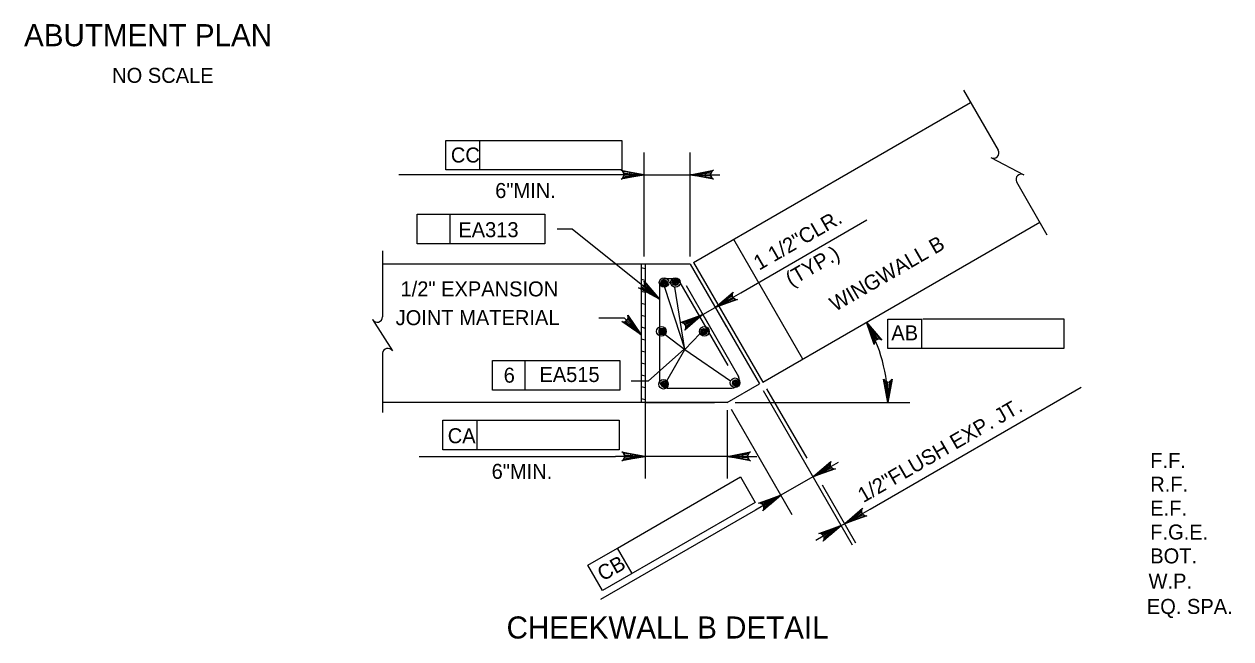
# Model space of a CAD drawing. Extents: x 638255 to 640306, y 296059 to 298435.
# Drawn here: x 638706.2 to 638947.5, y 297517 to 297639.9 of the extents above; entities that cross this region are included whole.
import ezdxf

# ---------------------------------------------------------------- set-up
doc = ezdxf.new("R2010")
doc.units = 0
for name, color, linetype in [('1', 7, 'Continuous'), ('Level 10', 7, 'Continuous'), ('Level 3', 7, 'Continuous'), ('Level 4', 7, 'Continuous'), ('Level 5', 7, 'Continuous')]:
    doc.layers.add(name, color=color, linetype=linetype)

# ---------------------------------------------------------------- blocks, each defined once
blk = doc.blocks.new('V')
at = {"layer": '1'}
blk.add_line((0, 0), (0, 0), dxfattribs=at)

msp = doc.modelspace()

# ---------------------------------------------------------------- linework, layer by layer
at = {"layer": 'Level 10'}
for p, q in [((638840.08, 297592.3), (638895.47, 297624.28)), ((638853.9, 297568.37), (638909.29, 297600.35)), ((638848.06, 297596.91), (638861.88, 297572.98)), ((638839.42, 297591.92), (638777.88, 297591.92)), ((638839.42, 297591.92), (638853.23, 297567.99)), ((638840.08, 297592.3), (638853.9, 297568.37)), ((638846.82, 297564.29), (638853.23, 297567.99)), ((638846.82, 297564.29), (638777.88, 297564.29)), ((638830.38, 297564.29), (638844.28, 297564.29))]:
    msp.add_line(p, q, dxfattribs=at)
at = {"layer": 'Level 3'}
for p, q in [((638790.51, 297616.67), (638797.34, 297616.67)), ((638790.51, 297610.78), (638790.51, 297616.67)), ((638797.34, 297610.78), (638797.34, 297616.67)), ((638797.34, 297616.67), (638825.74, 297616.67)), ((638825.74, 297616.67), (638825.74, 297610.78)), ((638830.21, 297593.45), (638830.21, 297614.24)), ((638839.42, 297593.45), (638839.42, 297614.24)), ((638827.26, 297609.83), (638781.13, 297609.83)), ((638825.74, 297610.78), (638790.51, 297610.78)), ((638830.21, 297609.83), (638839.42, 297609.83)), ((638842.36, 297609.83), (638845.31, 297609.83)), ((638784.82, 297601.9), (638810.31, 297601.9)), ((638784.82, 297596.01), (638784.82, 297601.9)), ((638791.4, 297596.01), (638791.4, 297601.9)), ((638810.31, 297601.9), (638810.31, 297596.01)), ((638849.51, 297586.22), (638874.73, 297600.78)), ((638815.77, 297598.94), (638812.82, 297598.94)), ((638833.26, 297584.95), (638815.77, 297598.94)), ((638810.31, 297596.01), (638784.82, 297596.01)), ((638829.61, 297591.92), (638829.61, 297564.29)), ((638829.61, 297591.3), (638830.38, 297591.09)), ((638830.38, 297591.92), (638830.38, 297562.75)), ((638829.61, 297588.91), (638830.38, 297588.71)), ((638834.79, 297589.04), (638835.98, 297589.04)), ((638837.31, 297588.27), (638846.91, 297571.65)), ((638829.61, 297586.53), (638830.38, 297586.32)), ((638833.26, 297587.5), (638833.26, 297568.7)), ((638834.26, 297587.31), (638838.31, 297574.9)), ((638838.31, 297574.9), (638836.3, 297587.32)), ((638838.56, 297587.65), (638849.05, 297569.47)), ((638842.36, 297586.83), (638846.62, 297579.45)), ((638844.4, 297583.28), (638849.51, 297586.22)), ((638829.61, 297584.15), (638830.38, 297583.94)), ((638841.91, 297581.84), (638844.41, 297583.28)), ((638826.28, 297581.15), (638821.13, 297581.15)), ((638829.61, 297577.81), (638826.28, 297581.15)), ((638829.61, 297581.76), (638830.38, 297581.56)), ((638841.53, 297582.51), (638843.5, 297579.09)), ((638878.9, 297575.04), (638878.9, 297580.94)), ((638878.9, 297580.94), (638885.71, 297580.94)), ((638885.73, 297575.04), (638885.73, 297580.94)), ((638885.94, 297580.99), (638914.18, 297580.99)), ((638914.13, 297580.94), (638914.13, 297575.04)), ((638829.61, 297579.38), (638830.38, 297579.17)), ((638829.61, 297577), (638830.38, 297576.79)), ((638834.36, 297577.86), (638838.31, 297574.9)), ((638838.31, 297574.9), (638841.37, 297578.1)), ((638829.61, 297574.61), (638830.38, 297574.4)), ((638838.27, 297575.03), (638831.02, 297568.51)), ((638834.72, 297568.63), (638838.31, 297574.9)), ((638838.31, 297574.9), (638847.48, 297568.59)), ((638914.13, 297575.04), (638878.9, 297575.04)), ((638799.85, 297572.65), (638825.33, 297572.65)), ((638799.85, 297566.76), (638799.85, 297572.65)), ((638806.42, 297566.76), (638806.42, 297572.65)), ((638825.33, 297572.65), (638825.33, 297566.76)), ((638829.61, 297572.23), (638830.38, 297572.02)), ((638831.02, 297568.51), (638827.61, 297568.51)), ((638829.61, 297569.84), (638830.38, 297569.64)), ((638825.33, 297566.76), (638799.85, 297566.76)), ((638829.61, 297567.46), (638830.38, 297567.25)), ((638834.79, 297567.17), (638847.73, 297567.17)), ((638854, 297566.66), (638871.8, 297535.82)), ((638854.67, 297567.04), (638862.69, 297553.15)), ((638875.36, 297542.98), (638917.55, 297567.34)), ((638829.61, 297565.08), (638830.38, 297564.87)), ((638848.36, 297564.29), (638883.34, 297564.29)), ((638830.38, 297562.75), (638830.38, 297549.09)), ((638846.82, 297562.75), (638846.82, 297549.09)), ((638847.59, 297562.96), (638859.75, 297541.89)), ((638789.95, 297560.73), (638796.79, 297560.73)), ((638789.95, 297554.84), (638789.95, 297560.73)), ((638796.79, 297554.84), (638796.79, 297560.73)), ((638796.79, 297560.73), (638825.19, 297560.73)), ((638825.19, 297560.73), (638825.19, 297554.84)), ((638825.19, 297554.84), (638789.95, 297554.84)), ((638785.18, 297553.5), (638824.48, 297553.5)), ((638827.43, 297553.5), (638824.48, 297553.5)), ((638846.82, 297553.5), (638830.38, 297553.5)), ((638849.77, 297553.5), (638852.72, 297553.5)), ((638863.95, 297549.42), (638869.06, 297552.37)), ((638824.84, 297535.18), (638849.43, 297549.38)), ((638849.43, 297549.38), (638852.38, 297544.28)), ((638863.95, 297549.42), (638857.54, 297545.72)), ((638865.78, 297547.8), (638872.47, 297536.21)), ((638857.54, 297545.72), (638852.44, 297542.77)), ((638852.44, 297542.77), (638821.49, 297524.91)), ((638852.38, 297544.28), (638821.87, 297526.66)), ((638870.26, 297540.04), (638875.36, 297542.98)), ((638869.6, 297539.65), (638864.49, 297536.71)), ((638869.6, 297539.65), (638870.26, 297540.03)), ((638818.92, 297531.76), (638824.84, 297535.18)), ((638827.78, 297530.08), (638824.84, 297535.18)), ((638821.87, 297526.66), (638818.92, 297531.76))]:
    msp.add_line(p, q, dxfattribs=at)
for points in [[(638830.21, 297609.83), (638825.56, 297608.95), (638825.92, 297609.2), (638826.1, 297609.51), (638826.15, 297609.83), (638826.1, 297610.14), (638825.92, 297610.45), (638825.56, 297610.7), (638830.21, 297609.83), (638825.92, 297610.45), (638826.1, 297610.14), (638830.21, 297609.83), (638826.15, 297609.83), (638826.1, 297609.51), (638830.21, 297609.83), (638825.92, 297609.2)], [(638839.42, 297609.83), (638844.07, 297610.7), (638843.71, 297610.45), (638843.53, 297610.14), (638843.47, 297609.83), (638843.53, 297609.51), (638843.71, 297609.2), (638844.07, 297608.95), (638839.42, 297609.83), (638843.71, 297609.2), (638843.53, 297609.51), (638839.42, 297609.83), (638843.47, 297609.83), (638843.53, 297610.14), (638839.42, 297609.83), (638843.71, 297610.45)], [(638833.26, 297584.95), (638829.08, 297587.18), (638829.51, 297587.15), (638829.85, 297587.28), (638830.09, 297587.49), (638830.24, 297587.76), (638830.29, 297588.12), (638830.17, 297588.54), (638833.26, 297584.95), (638830.29, 297588.12), (638830.24, 297587.76), (638833.26, 297584.95), (638830.09, 297587.49), (638829.85, 297587.28), (638833.26, 297584.95), (638829.51, 297587.15)], [(638844.4, 297583.28), (638848, 297586.36), (638847.81, 297585.96), (638847.81, 297585.6), (638847.92, 297585.3), (638848.12, 297585.06), (638848.43, 297584.88), (638848.87, 297584.85), (638844.4, 297583.28), (638848.43, 297584.88), (638848.12, 297585.06), (638844.4, 297583.28), (638847.92, 297585.3), (638847.81, 297585.6), (638844.4, 297583.28), (638847.81, 297585.96)], [(638829.61, 297577.81), (638825.71, 297580.49), (638826.14, 297580.41), (638826.49, 297580.5), (638826.75, 297580.68), (638826.93, 297580.94), (638827.02, 297581.29), (638826.94, 297581.72), (638829.61, 297577.81), (638827.02, 297581.29), (638826.93, 297580.94), (638829.61, 297577.81), (638826.75, 297580.68), (638826.49, 297580.5), (638829.61, 297577.81), (638826.14, 297580.41)], [(638841.91, 297581.84), (638838.32, 297578.76), (638838.51, 297579.15), (638838.51, 297579.51), (638838.4, 297579.81), (638838.2, 297580.05), (638837.88, 297580.23), (638837.45, 297580.27), (638841.91, 297581.84), (638837.88, 297580.23), (638838.2, 297580.05), (638841.91, 297581.84), (638838.4, 297579.81), (638838.51, 297579.51), (638841.91, 297581.84), (638838.51, 297579.15)], [(638874.62, 297580.34), (638877.7, 297576.75), (638877.31, 297576.93), (638876.95, 297576.94), (638876.65, 297576.83), (638876.41, 297576.62), (638876.23, 297576.31), (638876.19, 297575.87), (638874.62, 297580.34), (638876.23, 297576.31), (638876.41, 297576.62), (638874.62, 297580.34), (638876.65, 297576.83), (638876.95, 297576.94), (638874.62, 297580.34), (638877.31, 297576.93)], [(638878.92, 297564.29), (638878.05, 297568.94), (638878.3, 297568.58), (638878.61, 297568.4), (638878.92, 297568.34), (638879.24, 297568.4), (638879.55, 297568.58), (638879.8, 297568.94), (638878.92, 297564.29), (638879.55, 297568.58), (638879.24, 297568.4), (638878.92, 297564.29), (638878.92, 297568.34), (638878.61, 297568.4), (638878.92, 297564.29), (638878.3, 297568.58)], [(638830.38, 297553.5), (638825.73, 297552.63), (638826.08, 297552.88), (638826.27, 297553.19), (638826.32, 297553.5), (638826.27, 297553.82), (638826.08, 297554.13), (638825.73, 297554.38), (638830.38, 297553.5), (638826.08, 297554.13), (638826.27, 297553.82), (638830.38, 297553.5), (638826.32, 297553.5), (638826.27, 297553.19), (638830.38, 297553.5), (638826.08, 297552.88)], [(638846.82, 297553.5), (638851.47, 297554.38), (638851.12, 297554.13), (638850.93, 297553.82), (638850.88, 297553.5), (638850.93, 297553.19), (638851.12, 297552.88), (638851.47, 297552.63), (638846.82, 297553.5), (638851.12, 297552.88), (638850.93, 297553.19), (638846.82, 297553.5), (638850.88, 297553.5), (638850.93, 297553.82), (638846.82, 297553.5), (638851.12, 297554.13)], [(638863.95, 297549.42), (638867.55, 297552.5), (638867.36, 297552.11), (638867.36, 297551.75), (638867.46, 297551.45), (638867.67, 297551.21), (638867.98, 297551.03), (638868.42, 297550.99), (638863.95, 297549.42), (638867.98, 297551.03), (638867.67, 297551.21), (638863.95, 297549.42), (638867.46, 297551.45), (638867.36, 297551.75), (638863.95, 297549.42), (638867.36, 297552.11)], [(638857.54, 297545.72), (638853.95, 297542.64), (638854.14, 297543.03), (638854.14, 297543.4), (638854.03, 297543.69), (638853.83, 297543.94), (638853.51, 297544.11), (638853.08, 297544.15), (638857.54, 297545.72), (638853.51, 297544.11), (638853.83, 297543.94), (638857.54, 297545.72), (638854.03, 297543.69), (638854.14, 297543.4), (638857.54, 297545.72), (638854.14, 297543.03)], [(638870.26, 297540.04), (638873.85, 297543.12), (638873.67, 297542.72), (638873.66, 297542.36), (638873.77, 297542.06), (638873.97, 297541.82), (638874.29, 297541.64), (638874.72, 297541.6), (638870.26, 297540.04), (638874.29, 297541.64), (638873.97, 297541.82), (638870.26, 297540.04), (638873.77, 297542.06), (638873.66, 297542.36), (638870.26, 297540.04), (638873.67, 297542.72)], [(638869.6, 297539.65), (638866, 297536.57), (638866.19, 297536.97), (638866.19, 297537.33), (638866.08, 297537.62), (638865.88, 297537.87), (638865.57, 297538.04), (638865.13, 297538.08), (638869.6, 297539.65), (638865.57, 297538.04), (638865.88, 297537.87), (638869.6, 297539.65), (638866.08, 297537.62), (638866.19, 297537.33), (638869.6, 297539.65), (638866.19, 297536.97)]]:
    msp.add_lwpolyline(points, dxfattribs=at)
for points in [[(638827.26, 297610.32), (638827.26, 297609.33), (638830.21, 297609.83)], [(638842.36, 297610.32), (638842.36, 297609.33), (638839.42, 297609.83)], [(638846.71, 297585.18), (638847.21, 297584.32), (638844.41, 297583.28)], [(638827.43, 297554), (638827.43, 297553.01), (638830.38, 297553.5)], [(638849.77, 297554), (638849.77, 297553.01), (638846.82, 297553.5)], [(638866.26, 297551.32), (638866.75, 297550.47), (638863.95, 297549.42)], [(638854.75, 297544.67), (638855.24, 297543.82), (638857.54, 297545.72)], [(638872.57, 297541.93), (638873.06, 297541.08), (638870.26, 297540.03)], [(638866.8, 297538.6), (638867.29, 297537.75), (638869.6, 297539.65)]]:
    msp.add_lwpolyline(points, close=True, dxfattribs=at)
for centre in [(638834.18, 297588.27), (638836.45, 297588.27), (638833.64, 297578.5), (638842.24, 297578.5), (638834.06, 297567.93), (638848.37, 297568.22)]:
    msp.add_circle(centre, 0.96, dxfattribs=at)
for centre, radius, start, end in [((638834.79, 297587.5), 1.53, 90, 180), ((638835.98, 297587.5), 1.53, 30, 90), ((638846.82, 297564.29), 32.1, 359.9996, 30.0002), ((638834.79, 297568.7), 1.53, 180, 270), ((638847.73, 297568.7), 1.53, 270, 30)]:
    msp.add_arc(centre, radius, start, end, dxfattribs=at)
at = {"layer": 'Level 4'}
for p, q in [((638894.05, 297626.74), (638900.99, 297614.71)), ((638899.54, 297613.26), (638906.09, 297609.8)), ((638904.63, 297608.42), (638910.74, 297597.83)), ((638777.88, 297594.59), (638777.88, 297582.3)), ((638775.89, 297580.86), (638779.84, 297574.59)), ((638777.88, 297582.3), (638777.88, 297581.39)), ((638777.88, 297574.12), (638777.88, 297562.27))]:
    msp.add_line(p, q, dxfattribs=at)
for centre, start, end in [((638900.07, 297614.18), 240, 30), ((638905.6, 297608.86), 62.1328, 204.6714), ((638776.81, 297581.39), 210, 0), ((638778.94, 297574.03), 32.1328, 174.6714)]:
    msp.add_arc(centre, 1.06, start, end, dxfattribs=at)
at = {"layer": 'Level 5'}
for centre, radius in [((638834.19, 297588.16), 0.624), ((638834.19, 297588.16), 0.468), ((638834.19, 297588.16), 0.312), ((638834.19, 297588.16), 0.156), ((638836.44, 297588.28), 0.624), ((638836.44, 297588.28), 0.468), ((638836.44, 297588.28), 0.312), ((638836.44, 297588.28), 0.156), ((638833.79, 297578.48), 0.624), ((638833.79, 297578.48), 0.468), ((638833.79, 297578.48), 0.312), ((638833.79, 297578.48), 0.156), ((638842.14, 297578.42), 0.624), ((638842.14, 297578.42), 0.468), ((638842.14, 297578.42), 0.312), ((638842.14, 297578.42), 0.156), ((638834.25, 297567.98), 0.624), ((638848.48, 297568.16), 0.624), ((638848.48, 297568.16), 0.468), ((638834.25, 297567.98), 0.468), ((638834.25, 297567.98), 0.312), ((638834.25, 297567.98), 0.156), ((638848.48, 297568.16), 0.312), ((638848.48, 297568.16), 0.156)]:
    msp.add_circle(centre, radius, dxfattribs=at)

# ---------------------------------------------------------------- block references
at = {"layer": 'Level 3', "xscale": 0.7859001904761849, "yscale": 0.785900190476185}
msp.add_blockref('V', (638898.92, 297580.99), dxfattribs=at)

# ---------------------------------------------------------------- texts
at = {"layer": 'Level 3'}
for s, height, p in [('ABUTMENT PLAN', 4.4207, (638706.19, 297635.51)), ('NO SCALE', 3, (638723.81, 297628.19)), ('CC', 3, (638791.54, 297612.26)), ('6"MIN.', 3, (638800.4, 297605.16)), ('EA313', 3, (638793.03, 297597.33)), ('1/2" EXPANSION', 3.0001, (638781.47, 297585.49)), ('JOINT MATERIAL', 3.0001, (638780.5, 297579.74)), ('AB', 3, (638879.61, 297576.7)), ('6', 3, (638802.1, 297568.24)), ('EA515', 3, (638809.24, 297568.37)), ('CA', 3, (638790.91, 297556.13)), ('F.F.', 3, (638931.39, 297551.2)), ('6"MIN.', 3, (638799.69, 297549.01)), ('R.F.', 3, (638931.39, 297546.43)), ('E.F.', 3, (638931.39, 297541.66)), ('F.G.E.', 3, (638931.39, 297536.88)), ('BOT.', 3, (638931.39, 297532.11)), ('W.P.', 3, (638931.05, 297527.06)), ('EQ. SPA.', 3, (638930.71, 297522)), ('CHEEKWALL B DETAIL', 4.4207, (638802.68, 297517.08))]:
    msp.add_text(s, height=height, dxfattribs=at).set_placement(p)
for s, height, rotation, p in [('1 1/2"CLR.', 3, 30.0018, (638853.18, 297590.61)), ('WINGWALL B', 3, 30, (638868.38, 297582.36)), ('(TYP.)', 3, 30.0018, (638859.57, 297587.39)), ('1/2"FLUSH EXP. JT.', 3.0001, 30.0031, (638874.02, 297544.15)), ('CB', 3, 30, (638821.94, 297528.46))]:
    msp.add_text(s, height=height, rotation=rotation, dxfattribs=at).set_placement(p)

doc.saveas('drawing.dxf')
